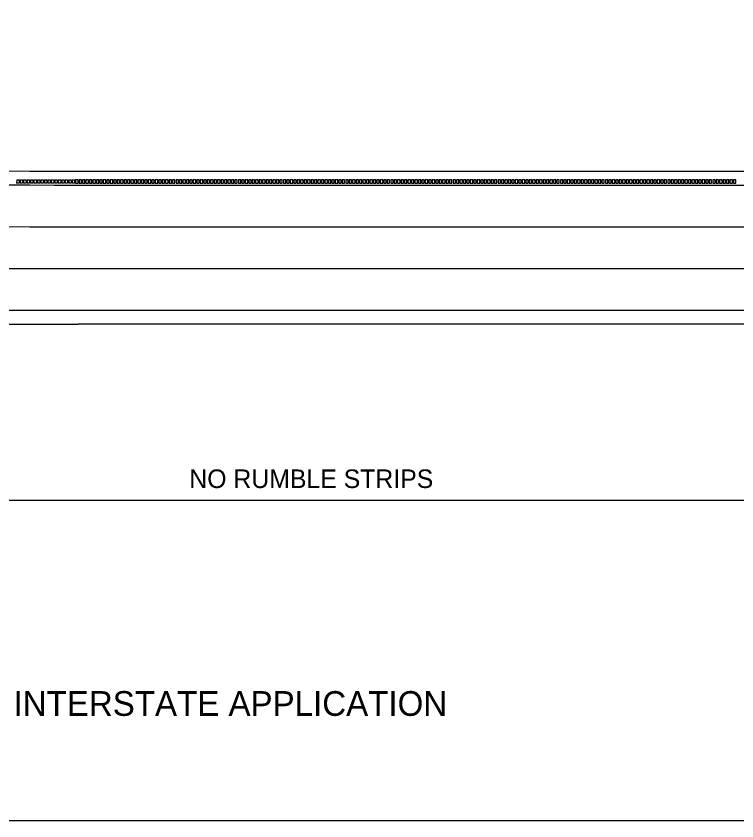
# Model space of a CAD drawing. Extents: x 49991.4 to 50021, y 49987.6 to 50011.4.
# Drawn here: x 50005.699 to 50008.031, y 49987.799 to 49990.402 of the extents above; entities that cross this region are included whole.
import ezdxf

# ---------------------------------------------------------------- set-up
doc = ezdxf.new("R2010")
doc.units = 0
for name, color, linetype in [('Level 1', 7, 'Continuous'), ('Level 2', 7, 'Continuous'), ('Level 3', 7, 'Continuous')]:
    doc.layers.add(name, color=color, linetype=linetype)

msp = doc.modelspace()

# ---------------------------------------------------------------- linework, layer by layer
at = {"layer": 'Level 1'}
for p, q in [((50005.9009, 49989.9006), (50012.4391, 49989.9007)), ((50005.7012, 49989.873), (50005.7011, 49989.8618)), ((50005.7089, 49989.8618), (50005.7011, 49989.8618)), ((50005.7012, 49989.873), (50005.709, 49989.873)), ((50005.709, 49989.873), (50005.7089, 49989.8618)), ((50005.7124, 49989.873), (50005.7123, 49989.8618)), ((50005.7201, 49989.8617), (50005.7123, 49989.8618)), ((50005.7124, 49989.873), (50005.7202, 49989.8729)), ((50005.7202, 49989.8729), (50005.7201, 49989.8617)), ((50005.7236, 49989.8729), (50005.7236, 49989.8617)), ((50005.7236, 49989.8729), (50005.7314, 49989.8729)), ((50005.7314, 49989.8617), (50005.7236, 49989.8617)), ((50005.7314, 49989.8729), (50005.7314, 49989.8617)), ((50005.7348, 49989.8729), (50005.7348, 49989.8617)), ((50005.7348, 49989.8729), (50005.7426, 49989.8729)), ((50005.7426, 49989.8617), (50005.7348, 49989.8617)), ((50005.7426, 49989.8729), (50005.7426, 49989.8617)), ((50005.746, 49989.8729), (50005.746, 49989.8617)), ((50005.746, 49989.8729), (50005.7538, 49989.8728)), ((50005.7538, 49989.8616), (50005.746, 49989.8617)), ((50005.7538, 49989.8728), (50005.7538, 49989.8616)), ((50005.7572, 49989.8728), (50005.7572, 49989.8616)), ((50005.7572, 49989.8728), (50005.765, 49989.8728)), ((50005.765, 49989.8616), (50005.7572, 49989.8616)), ((50005.765, 49989.8728), (50005.765, 49989.8616)), ((50005.7684, 49989.8728), (50005.7684, 49989.8616)), ((50005.7684, 49989.8728), (50005.7762, 49989.8728)), ((50005.7762, 49989.8616), (50005.7684, 49989.8616)), ((50005.7762, 49989.8728), (50005.7762, 49989.8616)), ((50005.7797, 49989.8728), (50005.7796, 49989.8616)), ((50005.7874, 49989.8615), (50005.7796, 49989.8616)), ((50005.7797, 49989.8728), (50005.7875, 49989.8727)), ((50005.7875, 49989.8727), (50005.7874, 49989.8615)), ((50005.7909, 49989.8727), (50005.7909, 49989.8615)), ((50005.7909, 49989.8727), (50005.7987, 49989.8727)), ((50005.7987, 49989.8615), (50005.7909, 49989.8615)), ((50005.7987, 49989.8727), (50005.7987, 49989.8615)), ((50005.8021, 49989.8727), (50005.8021, 49989.8615)), ((50005.8021, 49989.8727), (50005.8099, 49989.8727)), ((50005.8099, 49989.8615), (50005.8021, 49989.8615)), ((50005.8099, 49989.8727), (50005.8099, 49989.8615)), ((50005.8133, 49989.8727), (50005.8133, 49989.8615)), ((50005.8133, 49989.8727), (50005.8211, 49989.8727)), ((50005.8211, 49989.8615), (50005.8133, 49989.8615)), ((50005.8211, 49989.8727), (50005.8211, 49989.8615)), ((50005.8245, 49989.8727), (50005.8245, 49989.8615)), ((50005.8245, 49989.8727), (50005.8323, 49989.8727)), ((50005.8323, 49989.8615), (50005.8245, 49989.8615)), ((50005.8323, 49989.8727), (50005.8323, 49989.8615)), ((50005.8357, 49989.8727), (50005.8357, 49989.8615)), ((50005.8357, 49989.8727), (50005.8435, 49989.8726)), ((50005.8435, 49989.8614), (50005.8357, 49989.8615)), ((50005.8435, 49989.8726), (50005.8435, 49989.8614)), ((50005.847, 49989.8727), (50005.8469, 49989.8615)), ((50005.8547, 49989.8614), (50005.8469, 49989.8615)), ((50005.847, 49989.8727), (50005.8548, 49989.8726)), ((50005.8548, 49989.8726), (50005.8547, 49989.8614)), ((50005.8582, 49989.8726), (50005.8582, 49989.8614)), ((50005.8582, 49989.8726), (50005.866, 49989.8726)), ((50005.866, 49989.8614), (50005.8582, 49989.8614)), ((50005.866, 49989.8726), (50005.866, 49989.8614)), ((50005.8694, 49989.8726), (50005.8694, 49989.8614)), ((50005.8694, 49989.8726), (50005.8772, 49989.8726)), ((50005.8772, 49989.8614), (50005.8694, 49989.8614)), ((50005.8772, 49989.8726), (50005.8772, 49989.8614)), ((50005.8806, 49989.8726), (50005.8806, 49989.8614)), ((50005.8806, 49989.8726), (50005.8884, 49989.8726)), ((50005.8884, 49989.8614), (50005.8806, 49989.8614)), ((50005.8884, 49989.8726), (50005.8884, 49989.8614)), ((50005.9009, 49989.8556), (50012.4391, 49989.8557)), ((50005.9009, 49989.7206), (50012.4391, 49989.7207)), ((50005.9009, 49989.5856), (50012.4391, 49989.5857)), ((50003.6795, 49989.4506), (50005.8999, 49989.4506)), ((50005.8999, 49989.4506), (50008.7675, 49989.4506)), ((50003.6795, 49989.4056), (50005.8999, 49989.4056)), ((50008.7679, 49989.4055), (50005.8999, 49989.4056))]:
    msp.add_line(p, q, dxfattribs=at)
for points in [[(49999.3835, 49998.9992), (50016.7501, 49998.9992), (50016.7501, 49987.7988), (49999.3835, 49987.7988)], [(50005.8997, 49989.8726), (50005.8918, 49989.8726), (50005.8918, 49989.8614), (50005.8997, 49989.8614)], [(50005.9109, 49989.8726), (50005.903, 49989.8726), (50005.903, 49989.8614), (50005.9109, 49989.8614)], [(50005.9221, 49989.8726), (50005.9142, 49989.8726), (50005.9142, 49989.8614), (50005.9221, 49989.8614)], [(50005.9333, 49989.8726), (50005.9254, 49989.8726), (50005.9254, 49989.8614), (50005.9333, 49989.8614)], [(50005.9445, 49989.8726), (50005.9366, 49989.8726), (50005.9366, 49989.8614), (50005.9445, 49989.8614)], [(50005.9557, 49989.8726), (50005.9478, 49989.8726), (50005.9478, 49989.8614), (50005.9557, 49989.8614)], [(50005.9669, 49989.8726), (50005.959, 49989.8726), (50005.959, 49989.8614), (50005.9669, 49989.8614)], [(50005.9781, 49989.8726), (50005.9702, 49989.8726), (50005.9702, 49989.8614), (50005.9781, 49989.8614)], [(50005.9893, 49989.8726), (50005.9814, 49989.8726), (50005.9814, 49989.8614), (50005.9893, 49989.8614)], [(50006.0005, 49989.8726), (50005.9926, 49989.8726), (50005.9926, 49989.8614), (50006.0005, 49989.8614)], [(50006.0117, 49989.8726), (50006.0038, 49989.8726), (50006.0038, 49989.8614), (50006.0117, 49989.8614)], [(50006.0229, 49989.8726), (50006.015, 49989.8726), (50006.015, 49989.8614), (50006.0229, 49989.8614)], [(50006.0341, 49989.8726), (50006.0262, 49989.8726), (50006.0262, 49989.8614), (50006.0341, 49989.8614)], [(50006.0453, 49989.8726), (50006.0374, 49989.8726), (50006.0374, 49989.8614), (50006.0453, 49989.8614)], [(50006.0565, 49989.8726), (50006.0486, 49989.8726), (50006.0486, 49989.8614), (50006.0565, 49989.8614)], [(50006.0677, 49989.8726), (50006.0598, 49989.8726), (50006.0598, 49989.8614), (50006.0677, 49989.8614)], [(50006.0789, 49989.8726), (50006.071, 49989.8726), (50006.071, 49989.8614), (50006.0789, 49989.8614)], [(50006.0901, 49989.8726), (50006.0822, 49989.8726), (50006.0822, 49989.8614), (50006.0901, 49989.8614)], [(50006.1013, 49989.8726), (50006.0934, 49989.8726), (50006.0934, 49989.8614), (50006.1013, 49989.8614)], [(50006.1125, 49989.8726), (50006.1046, 49989.8726), (50006.1046, 49989.8614), (50006.1125, 49989.8614)], [(50006.1237, 49989.8726), (50006.1158, 49989.8726), (50006.1158, 49989.8614), (50006.1237, 49989.8614)], [(50006.1349, 49989.8726), (50006.127, 49989.8726), (50006.127, 49989.8614), (50006.1349, 49989.8614)], [(50006.1461, 49989.8726), (50006.1382, 49989.8726), (50006.1382, 49989.8614), (50006.1461, 49989.8614)], [(50006.1573, 49989.8726), (50006.1494, 49989.8726), (50006.1494, 49989.8614), (50006.1573, 49989.8614)], [(50006.1685, 49989.8726), (50006.1606, 49989.8726), (50006.1606, 49989.8614), (50006.1685, 49989.8614)], [(50006.1797, 49989.8726), (50006.1718, 49989.8726), (50006.1718, 49989.8614), (50006.1797, 49989.8614)], [(50006.1909, 49989.8726), (50006.183, 49989.8726), (50006.183, 49989.8614), (50006.1909, 49989.8614)], [(50006.2021, 49989.8726), (50006.1942, 49989.8726), (50006.1942, 49989.8614), (50006.2021, 49989.8614)], [(50006.2133, 49989.8726), (50006.2054, 49989.8726), (50006.2054, 49989.8614), (50006.2133, 49989.8614)], [(50006.2245, 49989.8726), (50006.2166, 49989.8726), (50006.2166, 49989.8614), (50006.2245, 49989.8614)], [(50006.2357, 49989.8726), (50006.2278, 49989.8726), (50006.2278, 49989.8614), (50006.2357, 49989.8614)], [(50006.2469, 49989.8726), (50006.239, 49989.8726), (50006.239, 49989.8614), (50006.2469, 49989.8614)], [(50006.2581, 49989.8726), (50006.2502, 49989.8726), (50006.2502, 49989.8614), (50006.2581, 49989.8614)], [(50006.2693, 49989.8726), (50006.2614, 49989.8726), (50006.2614, 49989.8614), (50006.2693, 49989.8614)], [(50006.2805, 49989.8726), (50006.2726, 49989.8726), (50006.2726, 49989.8614), (50006.2805, 49989.8614)], [(50006.2917, 49989.8726), (50006.2838, 49989.8726), (50006.2838, 49989.8614), (50006.2917, 49989.8614)], [(50006.3029, 49989.8726), (50006.295, 49989.8726), (50006.295, 49989.8614), (50006.3029, 49989.8614)], [(50006.3141, 49989.8726), (50006.3062, 49989.8726), (50006.3062, 49989.8614), (50006.3141, 49989.8614)], [(50006.3253, 49989.8726), (50006.3174, 49989.8726), (50006.3174, 49989.8614), (50006.3253, 49989.8614)], [(50006.3365, 49989.8726), (50006.3286, 49989.8726), (50006.3286, 49989.8614), (50006.3365, 49989.8614)], [(50006.3477, 49989.8726), (50006.3398, 49989.8726), (50006.3398, 49989.8614), (50006.3477, 49989.8614)], [(50006.3589, 49989.8726), (50006.351, 49989.8726), (50006.351, 49989.8614), (50006.3589, 49989.8614)], [(50006.3701, 49989.8726), (50006.3622, 49989.8726), (50006.3622, 49989.8614), (50006.3701, 49989.8614)], [(50006.3813, 49989.8726), (50006.3734, 49989.8726), (50006.3734, 49989.8614), (50006.3813, 49989.8614)], [(50006.3925, 49989.8726), (50006.3846, 49989.8726), (50006.3846, 49989.8614), (50006.3925, 49989.8614)], [(50006.4037, 49989.8726), (50006.3958, 49989.8726), (50006.3958, 49989.8614), (50006.4037, 49989.8614)], [(50006.4149, 49989.8726), (50006.407, 49989.8726), (50006.407, 49989.8614), (50006.4149, 49989.8614)], [(50006.4261, 49989.8726), (50006.4182, 49989.8726), (50006.4182, 49989.8614), (50006.4261, 49989.8614)], [(50006.4373, 49989.8726), (50006.4294, 49989.8726), (50006.4294, 49989.8614), (50006.4373, 49989.8614)], [(50006.4485, 49989.8726), (50006.4406, 49989.8726), (50006.4406, 49989.8614), (50006.4485, 49989.8614)], [(50006.4597, 49989.8726), (50006.4518, 49989.8726), (50006.4518, 49989.8614), (50006.4597, 49989.8614)], [(50006.4709, 49989.8726), (50006.463, 49989.8726), (50006.463, 49989.8614), (50006.4709, 49989.8614)], [(50006.4821, 49989.8726), (50006.4742, 49989.8726), (50006.4742, 49989.8614), (50006.4821, 49989.8614)], [(50006.4933, 49989.8726), (50006.4854, 49989.8726), (50006.4854, 49989.8614), (50006.4933, 49989.8614)], [(50006.5045, 49989.8726), (50006.4966, 49989.8726), (50006.4966, 49989.8614), (50006.5045, 49989.8614)], [(50006.5157, 49989.8726), (50006.5078, 49989.8726), (50006.5078, 49989.8614), (50006.5157, 49989.8614)], [(50006.5269, 49989.8726), (50006.519, 49989.8726), (50006.519, 49989.8614), (50006.5269, 49989.8614)], [(50006.5381, 49989.8726), (50006.5302, 49989.8726), (50006.5302, 49989.8614), (50006.5381, 49989.8614)], [(50006.5493, 49989.8726), (50006.5414, 49989.8726), (50006.5414, 49989.8614), (50006.5493, 49989.8614)], [(50006.5605, 49989.8726), (50006.5526, 49989.8726), (50006.5526, 49989.8614), (50006.5605, 49989.8614)], [(50006.5717, 49989.8726), (50006.5638, 49989.8726), (50006.5638, 49989.8614), (50006.5717, 49989.8614)], [(50006.5829, 49989.8726), (50006.575, 49989.8726), (50006.575, 49989.8614), (50006.5829, 49989.8614)], [(50006.5941, 49989.8726), (50006.5862, 49989.8726), (50006.5862, 49989.8614), (50006.5941, 49989.8614)], [(50006.6053, 49989.8726), (50006.5974, 49989.8726), (50006.5974, 49989.8614), (50006.6053, 49989.8614)], [(50006.6165, 49989.8726), (50006.6086, 49989.8726), (50006.6086, 49989.8614), (50006.6165, 49989.8614)], [(50006.6277, 49989.8726), (50006.6198, 49989.8726), (50006.6198, 49989.8614), (50006.6277, 49989.8614)], [(50006.6389, 49989.8726), (50006.631, 49989.8726), (50006.631, 49989.8614), (50006.6389, 49989.8614)], [(50006.6501, 49989.8726), (50006.6422, 49989.8726), (50006.6422, 49989.8614), (50006.6501, 49989.8614)], [(50006.6613, 49989.8726), (50006.6534, 49989.8726), (50006.6534, 49989.8614), (50006.6613, 49989.8614)], [(50006.6725, 49989.8726), (50006.6646, 49989.8726), (50006.6646, 49989.8614), (50006.6725, 49989.8614)], [(50006.6837, 49989.8726), (50006.6758, 49989.8726), (50006.6758, 49989.8614), (50006.6837, 49989.8614)], [(50006.6949, 49989.8726), (50006.687, 49989.8726), (50006.687, 49989.8614), (50006.6949, 49989.8614)], [(50006.7061, 49989.8726), (50006.6982, 49989.8726), (50006.6982, 49989.8614), (50006.7061, 49989.8614)], [(50006.7173, 49989.8726), (50006.7094, 49989.8726), (50006.7094, 49989.8614), (50006.7173, 49989.8614)], [(50006.7285, 49989.8726), (50006.7206, 49989.8726), (50006.7206, 49989.8614), (50006.7285, 49989.8614)], [(50006.7397, 49989.8726), (50006.7318, 49989.8726), (50006.7318, 49989.8614), (50006.7397, 49989.8614)], [(50006.7509, 49989.8726), (50006.743, 49989.8726), (50006.743, 49989.8614), (50006.7509, 49989.8614)], [(50006.7621, 49989.8726), (50006.7542, 49989.8726), (50006.7542, 49989.8614), (50006.7621, 49989.8614)], [(50006.7733, 49989.8726), (50006.7654, 49989.8726), (50006.7654, 49989.8614), (50006.7733, 49989.8614)], [(50006.7845, 49989.8726), (50006.7766, 49989.8726), (50006.7766, 49989.8614), (50006.7845, 49989.8614)], [(50006.7957, 49989.8726), (50006.7878, 49989.8726), (50006.7878, 49989.8614), (50006.7957, 49989.8614)], [(50006.8069, 49989.8726), (50006.799, 49989.8726), (50006.799, 49989.8614), (50006.8069, 49989.8614)], [(50006.8181, 49989.8726), (50006.8102, 49989.8726), (50006.8102, 49989.8614), (50006.8181, 49989.8614)], [(50006.8293, 49989.8726), (50006.8214, 49989.8726), (50006.8214, 49989.8614), (50006.8293, 49989.8614)], [(50006.8405, 49989.8726), (50006.8326, 49989.8726), (50006.8326, 49989.8614), (50006.8405, 49989.8614)], [(50006.8517, 49989.8726), (50006.8438, 49989.8726), (50006.8438, 49989.8614), (50006.8517, 49989.8614)], [(50006.8629, 49989.8726), (50006.855, 49989.8726), (50006.855, 49989.8614), (50006.8629, 49989.8614)], [(50006.8741, 49989.8726), (50006.8662, 49989.8726), (50006.8662, 49989.8614), (50006.8741, 49989.8614)], [(50006.8853, 49989.8726), (50006.8774, 49989.8726), (50006.8774, 49989.8614), (50006.8853, 49989.8614)], [(50006.8965, 49989.8726), (50006.8886, 49989.8726), (50006.8886, 49989.8614), (50006.8965, 49989.8614)], [(50006.9077, 49989.8726), (50006.8998, 49989.8726), (50006.8998, 49989.8614), (50006.9077, 49989.8614)], [(50006.9189, 49989.8726), (50006.911, 49989.8726), (50006.911, 49989.8614), (50006.9189, 49989.8614)], [(50006.9301, 49989.8726), (50006.9222, 49989.8726), (50006.9222, 49989.8614), (50006.9301, 49989.8614)], [(50006.9413, 49989.8726), (50006.9334, 49989.8726), (50006.9334, 49989.8614), (50006.9413, 49989.8614)], [(50006.9525, 49989.8726), (50006.9446, 49989.8726), (50006.9446, 49989.8614), (50006.9525, 49989.8614)], [(50006.9637, 49989.8726), (50006.9558, 49989.8726), (50006.9558, 49989.8614), (50006.9637, 49989.8614)], [(50006.9749, 49989.8726), (50006.967, 49989.8726), (50006.967, 49989.8614), (50006.9749, 49989.8614)], [(50006.9861, 49989.8726), (50006.9782, 49989.8726), (50006.9782, 49989.8614), (50006.9861, 49989.8614)], [(50006.9973, 49989.8726), (50006.9894, 49989.8726), (50006.9894, 49989.8614), (50006.9973, 49989.8614)], [(50007.0085, 49989.8726), (50007.0006, 49989.8726), (50007.0006, 49989.8614), (50007.0085, 49989.8614)], [(50007.0197, 49989.8726), (50007.0118, 49989.8726), (50007.0118, 49989.8614), (50007.0197, 49989.8614)], [(50007.0309, 49989.8726), (50007.023, 49989.8726), (50007.023, 49989.8614), (50007.0309, 49989.8614)], [(50007.0421, 49989.8726), (50007.0342, 49989.8726), (50007.0342, 49989.8614), (50007.0421, 49989.8614)], [(50007.0533, 49989.8726), (50007.0454, 49989.8726), (50007.0454, 49989.8614), (50007.0533, 49989.8614)], [(50007.0645, 49989.8726), (50007.0566, 49989.8726), (50007.0566, 49989.8614), (50007.0645, 49989.8614)], [(50007.0757, 49989.8726), (50007.0678, 49989.8726), (50007.0678, 49989.8614), (50007.0757, 49989.8614)], [(50007.0869, 49989.8726), (50007.079, 49989.8726), (50007.079, 49989.8614), (50007.0869, 49989.8614)], [(50007.0981, 49989.8726), (50007.0902, 49989.8726), (50007.0902, 49989.8614), (50007.0981, 49989.8614)], [(50007.1093, 49989.8726), (50007.1014, 49989.8726), (50007.1014, 49989.8614), (50007.1093, 49989.8614)], [(50007.1205, 49989.8726), (50007.1126, 49989.8726), (50007.1126, 49989.8614), (50007.1205, 49989.8614)], [(50007.1317, 49989.8726), (50007.1238, 49989.8726), (50007.1238, 49989.8614), (50007.1317, 49989.8614)], [(50007.1429, 49989.8726), (50007.135, 49989.8726), (50007.135, 49989.8614), (50007.1429, 49989.8614)], [(50007.1541, 49989.8726), (50007.1462, 49989.8726), (50007.1462, 49989.8614), (50007.1541, 49989.8614)], [(50007.1653, 49989.8726), (50007.1574, 49989.8726), (50007.1574, 49989.8614), (50007.1653, 49989.8614)], [(50007.1765, 49989.8726), (50007.1686, 49989.8726), (50007.1686, 49989.8614), (50007.1765, 49989.8614)], [(50007.1877, 49989.8726), (50007.1798, 49989.8726), (50007.1798, 49989.8614), (50007.1877, 49989.8614)], [(50007.1989, 49989.8726), (50007.191, 49989.8726), (50007.191, 49989.8614), (50007.1989, 49989.8614)], [(50007.2101, 49989.8726), (50007.2022, 49989.8726), (50007.2022, 49989.8614), (50007.2101, 49989.8614)], [(50007.2213, 49989.8726), (50007.2134, 49989.8726), (50007.2134, 49989.8614), (50007.2213, 49989.8614)], [(50007.2325, 49989.8726), (50007.2246, 49989.8726), (50007.2246, 49989.8614), (50007.2325, 49989.8614)], [(50007.2437, 49989.8726), (50007.2358, 49989.8726), (50007.2358, 49989.8614), (50007.2437, 49989.8614)], [(50007.2549, 49989.8726), (50007.247, 49989.8726), (50007.247, 49989.8614), (50007.2549, 49989.8614)], [(50007.2661, 49989.8726), (50007.2582, 49989.8726), (50007.2582, 49989.8614), (50007.2661, 49989.8614)], [(50007.2773, 49989.8726), (50007.2694, 49989.8726), (50007.2694, 49989.8614), (50007.2773, 49989.8614)], [(50007.2885, 49989.8726), (50007.2806, 49989.8726), (50007.2806, 49989.8614), (50007.2885, 49989.8614)], [(50007.2997, 49989.8726), (50007.2918, 49989.8726), (50007.2918, 49989.8614), (50007.2997, 49989.8614)], [(50007.3109, 49989.8726), (50007.303, 49989.8726), (50007.303, 49989.8614), (50007.3109, 49989.8614)], [(50007.3221, 49989.8726), (50007.3142, 49989.8726), (50007.3142, 49989.8614), (50007.3221, 49989.8614)], [(50007.3333, 49989.8726), (50007.3254, 49989.8726), (50007.3254, 49989.8614), (50007.3333, 49989.8614)], [(50007.3445, 49989.8726), (50007.3366, 49989.8726), (50007.3366, 49989.8614), (50007.3445, 49989.8614)], [(50007.3557, 49989.8726), (50007.3478, 49989.8726), (50007.3478, 49989.8614), (50007.3557, 49989.8614)], [(50007.3669, 49989.8726), (50007.359, 49989.8726), (50007.359, 49989.8614), (50007.3669, 49989.8614)], [(50007.3781, 49989.8726), (50007.3702, 49989.8726), (50007.3702, 49989.8614), (50007.3781, 49989.8614)], [(50007.3893, 49989.8726), (50007.3814, 49989.8726), (50007.3814, 49989.8614), (50007.3893, 49989.8614)], [(50007.4005, 49989.8726), (50007.3926, 49989.8726), (50007.3926, 49989.8614), (50007.4005, 49989.8614)], [(50007.4117, 49989.8726), (50007.4038, 49989.8726), (50007.4038, 49989.8614), (50007.4117, 49989.8614)], [(50007.4229, 49989.8726), (50007.415, 49989.8726), (50007.415, 49989.8614), (50007.4229, 49989.8614)], [(50007.4341, 49989.8726), (50007.4262, 49989.8726), (50007.4262, 49989.8614), (50007.4341, 49989.8614)], [(50007.4453, 49989.8726), (50007.4374, 49989.8726), (50007.4374, 49989.8614), (50007.4453, 49989.8614)], [(50007.4565, 49989.8726), (50007.4486, 49989.8726), (50007.4486, 49989.8614), (50007.4565, 49989.8614)], [(50007.4677, 49989.8726), (50007.4598, 49989.8726), (50007.4598, 49989.8614), (50007.4677, 49989.8614)], [(50007.4789, 49989.8726), (50007.471, 49989.8726), (50007.471, 49989.8614), (50007.4789, 49989.8614)], [(50007.4901, 49989.8726), (50007.4822, 49989.8726), (50007.4822, 49989.8614), (50007.4901, 49989.8614)], [(50007.5013, 49989.8726), (50007.4934, 49989.8726), (50007.4934, 49989.8614), (50007.5013, 49989.8614)], [(50007.5125, 49989.8726), (50007.5046, 49989.8726), (50007.5046, 49989.8614), (50007.5125, 49989.8614)], [(50007.5237, 49989.8726), (50007.5158, 49989.8726), (50007.5158, 49989.8614), (50007.5237, 49989.8614)], [(50007.5349, 49989.8726), (50007.527, 49989.8726), (50007.527, 49989.8614), (50007.5349, 49989.8614)], [(50007.5461, 49989.8726), (50007.5382, 49989.8726), (50007.5382, 49989.8614), (50007.5461, 49989.8614)], [(50007.5573, 49989.8726), (50007.5494, 49989.8726), (50007.5494, 49989.8614), (50007.5573, 49989.8614)], [(50007.5685, 49989.8726), (50007.5606, 49989.8726), (50007.5606, 49989.8614), (50007.5685, 49989.8614)], [(50007.5797, 49989.8726), (50007.5718, 49989.8726), (50007.5718, 49989.8614), (50007.5797, 49989.8614)], [(50007.5909, 49989.8726), (50007.583, 49989.8726), (50007.583, 49989.8614), (50007.5909, 49989.8614)], [(50007.6021, 49989.8726), (50007.5942, 49989.8726), (50007.5942, 49989.8614), (50007.6021, 49989.8614)], [(50007.6133, 49989.8726), (50007.6054, 49989.8726), (50007.6054, 49989.8614), (50007.6133, 49989.8614)], [(50007.6245, 49989.8726), (50007.6166, 49989.8726), (50007.6166, 49989.8614), (50007.6245, 49989.8614)], [(50007.6357, 49989.8726), (50007.6278, 49989.8726), (50007.6278, 49989.8614), (50007.6357, 49989.8614)], [(50007.6469, 49989.8726), (50007.639, 49989.8726), (50007.639, 49989.8614), (50007.6469, 49989.8614)], [(50007.6581, 49989.8726), (50007.6502, 49989.8726), (50007.6502, 49989.8614), (50007.6581, 49989.8614)], [(50007.6693, 49989.8726), (50007.6614, 49989.8726), (50007.6614, 49989.8614), (50007.6693, 49989.8614)], [(50007.6805, 49989.8726), (50007.6726, 49989.8726), (50007.6726, 49989.8614), (50007.6805, 49989.8614)], [(50007.6917, 49989.8726), (50007.6838, 49989.8726), (50007.6838, 49989.8614), (50007.6917, 49989.8614)], [(50007.7029, 49989.8726), (50007.695, 49989.8726), (50007.695, 49989.8614), (50007.7029, 49989.8614)], [(50007.7141, 49989.8726), (50007.7062, 49989.8726), (50007.7062, 49989.8614), (50007.7141, 49989.8614)], [(50007.7253, 49989.8726), (50007.7174, 49989.8726), (50007.7174, 49989.8614), (50007.7253, 49989.8614)], [(50007.7365, 49989.8726), (50007.7286, 49989.8726), (50007.7286, 49989.8614), (50007.7365, 49989.8614)], [(50007.7477, 49989.8726), (50007.7398, 49989.8726), (50007.7398, 49989.8614), (50007.7477, 49989.8614)], [(50007.7589, 49989.8726), (50007.751, 49989.8726), (50007.751, 49989.8614), (50007.7589, 49989.8614)], [(50007.7701, 49989.8726), (50007.7622, 49989.8726), (50007.7622, 49989.8614), (50007.7701, 49989.8614)], [(50007.7813, 49989.8726), (50007.7734, 49989.8726), (50007.7734, 49989.8614), (50007.7813, 49989.8614)], [(50007.7925, 49989.8726), (50007.7846, 49989.8726), (50007.7846, 49989.8614), (50007.7925, 49989.8614)], [(50007.8037, 49989.8726), (50007.7958, 49989.8726), (50007.7958, 49989.8614), (50007.8037, 49989.8614)], [(50007.8149, 49989.8726), (50007.807, 49989.8726), (50007.807, 49989.8614), (50007.8149, 49989.8614)], [(50007.8261, 49989.8726), (50007.8182, 49989.8726), (50007.8182, 49989.8614), (50007.8261, 49989.8614)], [(50007.8373, 49989.8726), (50007.8294, 49989.8726), (50007.8294, 49989.8614), (50007.8373, 49989.8614)], [(50007.8485, 49989.8726), (50007.8406, 49989.8726), (50007.8406, 49989.8614), (50007.8485, 49989.8614)], [(50007.8597, 49989.8726), (50007.8518, 49989.8726), (50007.8518, 49989.8614), (50007.8597, 49989.8614)], [(50007.8709, 49989.8726), (50007.863, 49989.8726), (50007.863, 49989.8614), (50007.8709, 49989.8614)], [(50007.8821, 49989.8726), (50007.8742, 49989.8726), (50007.8742, 49989.8614), (50007.8821, 49989.8614)], [(50007.8933, 49989.8726), (50007.8854, 49989.8726), (50007.8854, 49989.8614), (50007.8933, 49989.8614)], [(50007.9045, 49989.8726), (50007.8966, 49989.8726), (50007.8966, 49989.8614), (50007.9045, 49989.8614)], [(50007.9157, 49989.8726), (50007.9078, 49989.8726), (50007.9078, 49989.8614), (50007.9157, 49989.8614)], [(50007.9269, 49989.8726), (50007.919, 49989.8726), (50007.919, 49989.8614), (50007.9269, 49989.8614)], [(50007.9381, 49989.8726), (50007.9302, 49989.8726), (50007.9302, 49989.8614), (50007.9381, 49989.8614)], [(50007.9493, 49989.8726), (50007.9414, 49989.8726), (50007.9414, 49989.8614), (50007.9493, 49989.8614)], [(50007.9605, 49989.8726), (50007.9526, 49989.8726), (50007.9526, 49989.8614), (50007.9605, 49989.8614)], [(50007.9717, 49989.8726), (50007.9638, 49989.8726), (50007.9638, 49989.8614), (50007.9717, 49989.8614)], [(50007.9829, 49989.8726), (50007.975, 49989.8726), (50007.975, 49989.8614), (50007.9829, 49989.8614)], [(50007.9941, 49989.8726), (50007.9862, 49989.8726), (50007.9862, 49989.8614), (50007.9941, 49989.8614)], [(50008.0053, 49989.8726), (50007.9974, 49989.8726), (50007.9974, 49989.8614), (50008.0053, 49989.8614)], [(50008.0165, 49989.8726), (50008.0086, 49989.8726), (50008.0086, 49989.8614), (50008.0165, 49989.8614)], [(50008.0277, 49989.8726), (50008.0198, 49989.8726), (50008.0198, 49989.8614), (50008.0277, 49989.8614)]]:
    msp.add_lwpolyline(points, close=True, dxfattribs=at)
for radius in [52.2151, 52.2601, 52.3951, 52.5301]:
    msp.add_arc((50005.9009, 50042.1157), radius, 264.5, 270, dxfattribs=at)
at = {"layer": 'Level 3'}
msp.add_line((50011.6249, 49988.8356), (50001.8014, 49988.8356), dxfattribs=at)

# ---------------------------------------------------------------- texts
at = {"layer": 'Level 2'}
for s, height, p in [('NO RUMBLE STRIPS', 0.06, (50006.2597, 49988.8756)), ('INTERSTATE APPLICATION', 0.08, (50005.691, 49988.1386))]:
    msp.add_text(s, height=height, dxfattribs=at).set_placement(p)

doc.saveas('drawing.dxf')
